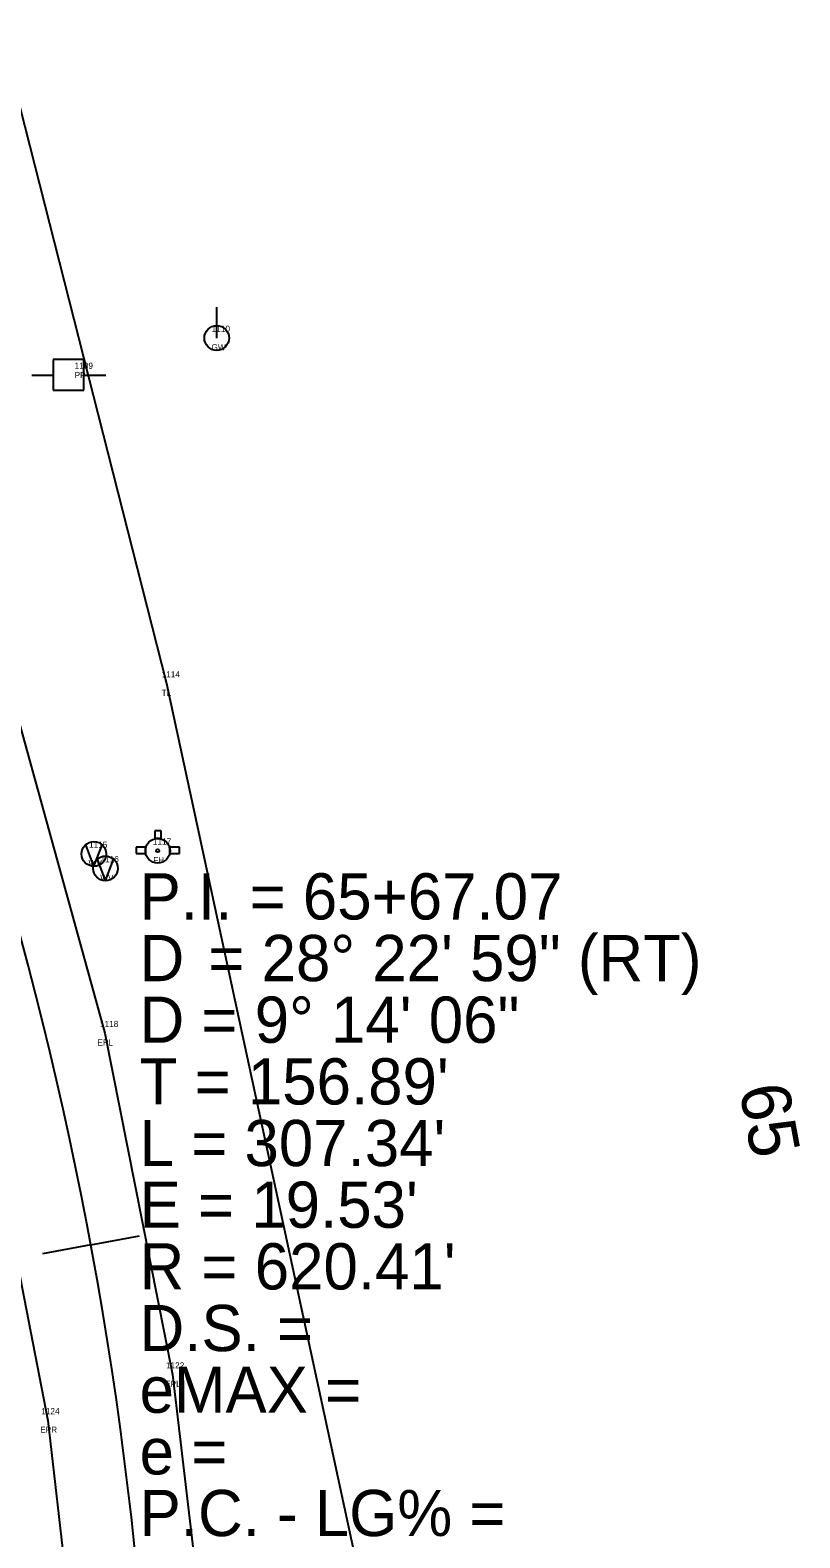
# Model space of a CAD drawing. Extents: x 2432632 to 2433497, y 684847 to 688233.
# Drawn here: x 2433136.2 to 2433261.1, y 686295.7 to 686540.2 of the extents above; entities that cross this region are included whole.
import ezdxf

# ---------------------------------------------------------------- set-up
doc = ezdxf.new("R2010")
doc.units = 0
for name, color, linetype in [('RD_EX_Road', 7, 'Continuous'), ('RD_EX_Road_txCode', 7, 'Continuous'), ('RD_EX_UT', 7, 'Continuous'), ('RD_EX_UT_txCode', 7, 'Continuous'), ('RD_EX_VEG', 7, 'Continuous'), ('RD_EX_VEG_txCode', 7, 'Continuous'), ('RD_HC_Cl', 7, 'Continuous'), ('RD_HC_Data', 7, 'Continuous'), ('RD_HC_Data_Tic', 7, 'Continuous'), ('RD_HC_TX_Sta50', 7, 'Continuous'), ('RD_SMD_Locator', 7, 'Continuous')]:
    doc.layers.add(name, color=color, linetype=linetype)

msp = doc.modelspace()

# ---------------------------------------------------------------- linework, layer by layer
at = {"layer": 'RD_EX_Road'}
for points in [[(2433066.06, 686565.78), (2433098.73, 686469.74), (2433113.88, 686422.91), (2433127.93, 686372.14), (2433139.1, 686314.76), (2433144.47, 686268.02), (2433145.44, 686213), (2433142.32, 686164.92), (2433135.44, 686115.75), (2433128.09, 686081.14)], [(2433088.99, 686562.5), (2433099.45, 686534.09), (2433118.26, 686478), (2433133.83, 686430.29), (2433148.35, 686377.56), (2433159.33, 686322.19), (2433165.5, 686270.06), (2433166.43, 686212.82), (2433163.02, 686162.81), (2433156.19, 686111.14), (2433152.88, 686076.43)]]:
    msp.add_lwpolyline(points, dxfattribs=at)
at = {"layer": 'RD_EX_UT'}
for p, q in [((2433166.51, 686490.3), (2433166.51, 686495.3)), ((2433144.95, 686486.82), (2433139.95, 686486.82)), ((2433139.95, 686486.82), (2433139.95, 686481.82)), ((2433144.95, 686481.82), (2433144.95, 686486.82)), ((2433136.52, 686484.26), (2433139.99, 686484.26)), ((2433144.88, 686484.26), (2433148.52, 686484.26)), ((2433139.95, 686481.82), (2433144.95, 686481.82)), ((2433156.48, 686410.37), (2433156.48, 686409.09)), ((2433157.48, 686410.37), (2433156.48, 686410.37)), ((2433157.48, 686409.07), (2433157.48, 686410.37)), ((2433146.58, 686404.63), (2433145.27, 686408.12)), ((2433146.58, 686404.63), (2433147.9, 686408.08)), ((2433155.02, 686407.72), (2433153.46, 686407.72)), ((2433153.46, 686407.72), (2433153.46, 686406.72)), ((2433160.46, 686407.72), (2433158.85, 686407.72)), ((2433160.46, 686406.72), (2433160.46, 686407.72)), ((2433148.46, 686402.3), (2433147.16, 686405.78)), ((2433148.46, 686402.3), (2433149.79, 686405.74)), ((2433153.46, 686406.72), (2433154.98, 686406.72)), ((2433158.89, 686406.72), (2433160.46, 686406.72))]:
    msp.add_line(p, q, dxfattribs=at)
for centre, radius in [((2433166.51, 686490.3), 2), ((2433146.58, 686406.63), 2), ((2433156.93, 686407.15), 2), ((2433156.93, 686407.15), 0.25), ((2433148.46, 686404.29), 2)]:
    msp.add_circle(centre, radius, dxfattribs=at)
for start, end in [(163.3387, 192.315), (74.2455, 103.2128), (347.685, 16.6613)]:
    msp.add_arc((2433156.93, 686407.15), 2, start, end, dxfattribs=at)
at = {"layer": 'RD_EX_VEG'}
msp.add_lwpolyline([(2433166.25, 688082.87), (2433111.93, 687876.69), (2433067.75, 687703.46), (2433065.05, 687678.03), (2433052.74, 687645.62), (2433005.45, 687469.88), (2432979.96, 687326.61), (2432966.8, 687267.34), (2432959.05, 687210.65), (2432959.25, 687071.62), (2432974.82, 687014.37), (2432998.13, 686938.9), (2433012.99, 686878.7), (2433054.45, 686782.35), (2433123.54, 686586.06), (2433129.82, 686546.35), (2433158.34, 686434.26), (2433192.79, 686274.67), (2433189.42, 686162.6), (2433197.4, 686074.41)], dxfattribs=at)
at = {"layer": 'RD_HC_Cl'}
msp.add_arc((2432536.11, 686229.97), 620.41, 350.43349, 18.81644, dxfattribs=at)
at = {"layer": 'RD_HC_Data_Tic'}
for q in [(2433138.23, 686341.8), (2433153.96, 686344.72)]:
    msp.add_line((2433146.09, 686343.26), q, dxfattribs=at)
at = {"layer": 'RD_SMD_Locator'}
for centre in [(2433158.34, 686434.26), (2433148.35, 686377.56), (2433159.33, 686322.19), (2433139.1, 686314.76)]:
    msp.add_circle(centre, 0.001, dxfattribs=at)

# ---------------------------------------------------------------- texts
at = {"layer": 'RD_EX_Road_txCode'}
for s, p in [('1118', (2433147.57, 686378.56)), ('EPL', (2433147.15, 686375.56)), ('1122', (2433158.27, 686323.19)), ('EPL', (2433158.13, 686320.19)), ('1124', (2433138.04, 686315.76)), ('EPR', (2433137.87, 686312.76))]:
    msp.add_text(s, height=1, dxfattribs=at).set_placement(p)
at = {"layer": 'RD_EX_UT_txCode'}
for s, p in [('1110', (2433165.69, 686491.3)), ('GW', (2433165.66, 686488.3)), ('1109', (2433143.46, 686485.31)), ('PP', (2433143.46, 686483.81)), ('1115', (2433145.8, 686407.63)), ('1117', (2433156.15, 686408.15)), ('WV', (2433145.72, 686404.63)), ('1116', (2433147.66, 686405.29)), ('FH', (2433156.2, 686405.15)), ('WV', (2433147.61, 686402.29))]:
    msp.add_text(s, height=1, dxfattribs=at).set_placement(p)
at = {"layer": 'RD_EX_VEG_txCode'}
for s, p in [('1114', (2433157.56, 686435.26)), ('TL', (2433157.57, 686432.26))]:
    msp.add_text(s, height=1, dxfattribs=at).set_placement(p)
at = {"layer": 'RD_HC_Data'}
for s, p in [('P.I. = 65+67.07', (2433154, 686396)), ('D', (2433154, 686386)), ('    = 28%%d 22\' 59" (RT)', (2433154, 686386)), ('D = 9%%d 14\' 06"', (2433154, 686376)), ("T = 156.89'", (2433154, 686366)), ("L = 307.34'", (2433154, 686356)), ("E = 19.53'", (2433154, 686346)), ("R = 620.41'", (2433154, 686336)), ('D.S. = ', (2433154, 686326)), ('eMAX = ', (2433154, 686316)), ('e = ', (2433154, 686306)), ('P.C. - LG% = ', (2433154, 686296))]:
    msp.add_text(s, height=7.5, dxfattribs=at).set_placement(p)
at = {"layer": 'RD_HC_TX_Sta50'}
msp.add_text('65', height=8, rotation=280.5215, dxfattribs=at).set_placement((2433251.23, 686368.64))

doc.saveas('drawing.dxf')
